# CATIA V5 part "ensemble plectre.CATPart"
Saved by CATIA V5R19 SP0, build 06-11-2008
Part number: F2
Revision: ANY
Definition: UNKNOWN
Nomenclature: F2
Source: Unknown
Bounding box of the stored display mesh (mm): x -12.5 to 12.501, y -26.5 to 10.545, z -24.25 to 24.25
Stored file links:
  I:\mediator\ensemble plectre.CATPart
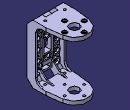
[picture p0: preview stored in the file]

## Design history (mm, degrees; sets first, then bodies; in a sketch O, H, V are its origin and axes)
Solid1: solid without history
Set1 "FaceKO#NONE#3497"
  DatumSurface1 "Sur3497_1"
  Line1 "Crv3497_1": stored without definition
Set2 "FaceKO#NONE#11526"
  DatumSurface2 "Sur11526_1"
  Line2 "Crv11526_1": stored without definition
Set3
  Sketch1 on face of Solid1, origin (0, -26.5, 0), H (1, 0, 0), V (0, 0, 1)
    circle A1 centre (8, 16) radius 1
    circle A2 centre (-8, 16) radius 1
    circle A3 centre (8, -16) radius 1
    circle A4 centre (-8, -16) radius 1
    circle A5 centre (8, 16) radius 1.4142
    circle A6 centre (-8, 16) radius 1.4142
    circle A7 centre (8, -16) radius 1.4142
    circle A8 centre (-8, -16) radius 1.4142
    radius A3 = 1
    radius A4 = 1
    radius A2 = 1
    radius A1 = 1
Body1 "Mirror6" (main body)
  Pad1: profile Sketch1, direction (0, 1, 0), length 2.5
